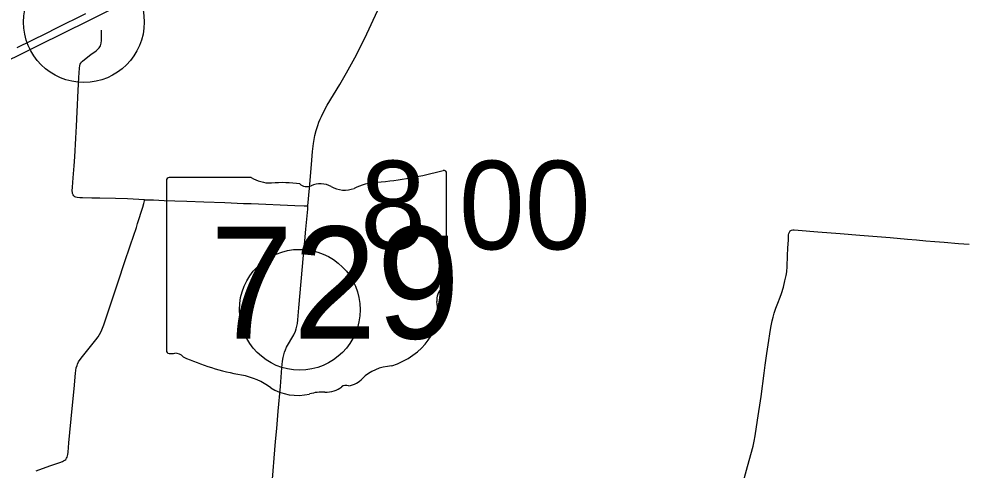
# Model space of a CAD drawing. Extents: x 1597222 to 1925846, y 496284 to 911751.
# Drawn here: x 1665653 to 1677369, y 592215 to 597821 of the extents above; entities that cross this region are included whole.
import ezdxf

# ---------------------------------------------------------------- set-up
doc = ezdxf.new("R2010")
doc.units = 0
for name, color, linetype in [('Default', 7, 'Continuous'), ('GM_X_County_Road', 7, 'Continuous'), ('GM_X_Interstate_Route', 7, 'Continuous'), ('GM_X_State_Route', 7, 'Continuous'), ('GM_X_State_Shield', 7, 'Continuous'), ('GM_X_Township_Road', 7, 'Continuous')]:
    doc.layers.add(name, color=color, linetype=linetype)

msp = doc.modelspace()

# ---------------------------------------------------------------- linework, layer by layer
at = {"layer": 'Default'}
for centre in [(1666460, 597780), (1666460, 597780), (1669142, 594208), (1669142, 594208)]:
    msp.add_circle(centre, 750, dxfattribs=at)
at = {"layer": 'GM_X_County_Road'}
msp.add_lwpolyline([(1674605, 591897), (1674704, 592261), (1674773, 592513), (1674788, 592577), (1674800, 592641), (1674829, 592836), (1674871, 593128), (1674910, 593420), (1674923, 593518), (1674943, 593664), (1674968, 593826), (1674980, 593907), (1674994, 593988), (1675011, 594069), (1675022, 594117), (1675035, 594164), (1675056, 594227), (1675080, 594288), (1675109, 594364), (1675125, 594411), (1675149, 594489), (1675169, 594568), (1675183, 594632), (1675190, 594680), (1675195, 594745), (1675202, 594876), (1675206, 594975), (1675211, 595073), (1675213, 595122), (1675214, 595139), (1675217, 595156), (1675223, 595172), (1675234, 595186), (1675249, 595196), (1675266, 595201), (1675283, 595201), (1675332, 595197), (1675577, 595176), (1675855, 595154), (1676100, 595134), (1676476, 595104), (1676689, 595086), (1676803, 595077), (1676917, 595065), (1677031, 595056), (1677146, 595047), (1677326, 595031), (1677456, 595021)], dxfattribs=at)
at = {"layer": 'GM_X_Interstate_Route'}
for points in [[(1664380, 596744), (1665760, 597422), (1666351, 597716), (1666379, 597730), (1666540, 597810), (1666769, 597923), (1667210, 598141), (1669437, 599241), (1669660, 599351), (1669859, 599450), (1670569, 599801), (1670626, 599828)], [(1665631, 597466), (1665996, 597645), (1666117, 597705), (1666485, 597888)]]:
    msp.add_lwpolyline(points, dxfattribs=at)
at = {"layer": 'GM_X_State_Route'}
msp.add_lwpolyline([(1668794, 591998), (1668841, 592570), (1668856, 592732), (1668856, 592733), (1668874, 592946), (1668901, 593256), (1668919, 593485), (1668927, 593567), (1668934, 593616), (1668942, 593648), (1668951, 593680), (1668963, 593711), (1668977, 593741), (1669001, 593784), (1669044, 593854), (1669067, 593897), (1669087, 593941), (1669097, 593972), (1669106, 594003), (1669112, 594035), (1669119, 594083), (1669131, 594230), (1669159, 594557), (1669190, 594884), (1669206, 595063), (1669219, 595210), (1669241, 595456), (1669244, 595499), (1669262, 595717), (1669286, 596011), (1669301, 596175), (1669312, 596273), (1669319, 596321), (1669329, 596370), (1669345, 596434), (1669365, 596496), (1669380, 596537), (1669394, 596573), (1669410, 596610), (1669428, 596646), (1669484, 596750), (1669560, 596878), (1669638, 597006), (1669724, 597151), (1669824, 597335), (1669951, 597581), (1670185, 598095)], dxfattribs=at)
at = {"layer": 'GM_X_State_Shield'}
for p, q in [((1667486, 595813), (1667486, 593700)), ((1668539, 595849), (1667520, 595849)), ((1670966, 594796), (1670966, 595902)), ((1670966, 594797), (1670966, 594796))]:
    msp.add_line(p, q, dxfattribs=at)
for centre, major_axis, start_param, end_param in [((1669726, 598730), (3691, 0), 4.814394, 5.042369), ((1670927, 595906), (38.7, 0), 6.141152, 7.989035), ((1667526, 595818), (40.3, 0), 1.712693, 3.28349), ((1668782, 596095), (391, 0), 4.042523, 4.731795), ((1670197, 595204), (743, 0), 1.699011, 2.107814), ((1668912, 594663), (1404, 0), 1.404758, 1.657858), ((1669230, 595828), (113, 0), 3.836095, 5.185415), ((1669396, 595584), (235, 0), 0.950623, 2.079405), ((1669699, 595919), (282, 0), 4.081561, 5.145723), ((1670957, 594715), (60, 0), 1.883978, 3.671073), ((1670925, 594792), (41.5, 0), 5.05454, 6.418171), ((1670576, 594575), (360, 0), 5.934695, 6.695948), ((1671105, 594334), (262, 0), 2.387724, 3.262537), ((1669933, 594193), (923, 0), 5.101752, 6.440018), ((1667526, 593695), (40.7, 0), 3.00124, 4.508301), ((1667532, 593911), (310, 0), 4.665946, 4.897461), ((1667596, 593578), (112, 0), 0.519207, 1.627899), ((1669009, 595477), (2665, 0), 4.195997, 4.488961), ((1670322, 593106), (506, 0), 1.647645, 2.488434), ((1668214, 592750), (834, 0), 0.823519, 1.323587), ((1669682, 593495), (298, 0), 4.937069, 5.64225), ((1669116, 593567), (529, 0), 4.026481, 4.996735), ((1669461, 593409), (282, 0), 4.691044, 5.507374), ((1669716, 593204), (79.4, 0), 1.147584, 2.315152), ((1669422, 592837), (435, 0), 1.495662, 1.94098)]:
    msp.add_ellipse(centre, major_axis=major_axis, ratio=0.8, start_param=start_param, end_param=end_param, dxfattribs=at)
at = {"layer": 'GM_X_Township_Road'}
for points in [[(1667215, 595573), (1667003, 595585), (1666855, 595589), (1666658, 595592), (1666559, 595594), (1666444, 595596), (1666411, 595597), (1666378, 595600), (1666362, 595605), (1666348, 595612), (1666335, 595622), (1666326, 595635), (1666320, 595650), (1666317, 595666), (1666316, 595683), (1666319, 595732), (1666329, 595847), (1666340, 595994), (1666347, 596109), (1666360, 596339), (1666367, 596486), (1666377, 596667), (1666389, 596929), (1666398, 597093), (1666406, 597208), (1666410, 597241), (1666414, 597257), (1666421, 597272), (1666431, 597285), (1666442, 597297), (1666467, 597318), (1666546, 597377), (1666613, 597425), (1666626, 597435), (1666637, 597447), (1666648, 597459), (1666658, 597472), (1666666, 597486), (1666671, 597502), (1666673, 597518), (1666677, 597551), (1666678, 597633), (1666678, 597682)], [(1665869, 592206), (1666039, 592267), (1666163, 592310), (1666194, 592322), (1666209, 592329), (1666222, 592338), (1666234, 592349), (1666244, 592362), (1666251, 592376), (1666256, 592392), (1666260, 592408), (1666264, 592440), (1666273, 592555), (1666314, 592979), (1666338, 593224), (1666356, 593420), (1666360, 593453), (1666366, 593485), (1666375, 593517), (1666380, 593532), (1666395, 593561), (1666413, 593589), (1666442, 593628), (1666607, 593832), (1666637, 593872), (1666655, 593899), (1666671, 593928), (1666685, 593957), (1666708, 594019), (1666796, 594283), (1666894, 594579), (1666962, 594781), (1667041, 595014), (1667077, 595123), (1667114, 595231), (1667128, 595278), (1667191, 595482), (1667205, 595529), (1667209, 595545), (1667212, 595560), (1667215, 595573)], [(1667215, 595573), (1667237, 595572), (1667261, 595572), (1667325, 595571), (1667458, 595566), (1667589, 595561), (1667737, 595555), (1667950, 595547), (1668212, 595538), (1668441, 595529), (1668540, 595526), (1668720, 595520), (1668900, 595512), (1669080, 595504), (1669195, 595500), (1669211, 595500), (1669244, 595499)]]:
    msp.add_lwpolyline(points, dxfattribs=at)

# ---------------------------------------------------------------- texts
at = {"layer": 'Default'}
msp.add_text('8.00', height=1100, dxfattribs=at).set_placement((1669892, 594958))
msp.add_text('8.00', height=1100, dxfattribs=at).set_placement((1669892, 594958))
at = {"layer": 'GM_X_State_Shield'}
msp.add_text('729', height=1392.2, dxfattribs=at).set_placement((1668026, 593849))

doc.saveas('drawing.dxf')
